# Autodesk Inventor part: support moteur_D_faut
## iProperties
Created: 2011-10
Part Number: support moteur_D_faut
Document SubType Name: Modeling
Designer: Bruno
Author: Bruno
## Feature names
1. Base1
